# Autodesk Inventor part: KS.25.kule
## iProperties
Created: 2010-04
Part Number: KS.25.kule
Document SubType Name: Modeling
Designer: TB
Mass: 11.1394 g
Surface Area: 58.2514 cm^2
Volume: 11.1394 cm^3
Density: 1 g/cm^3
Author: TB
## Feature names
1. Derived Body1 [Tagging]
